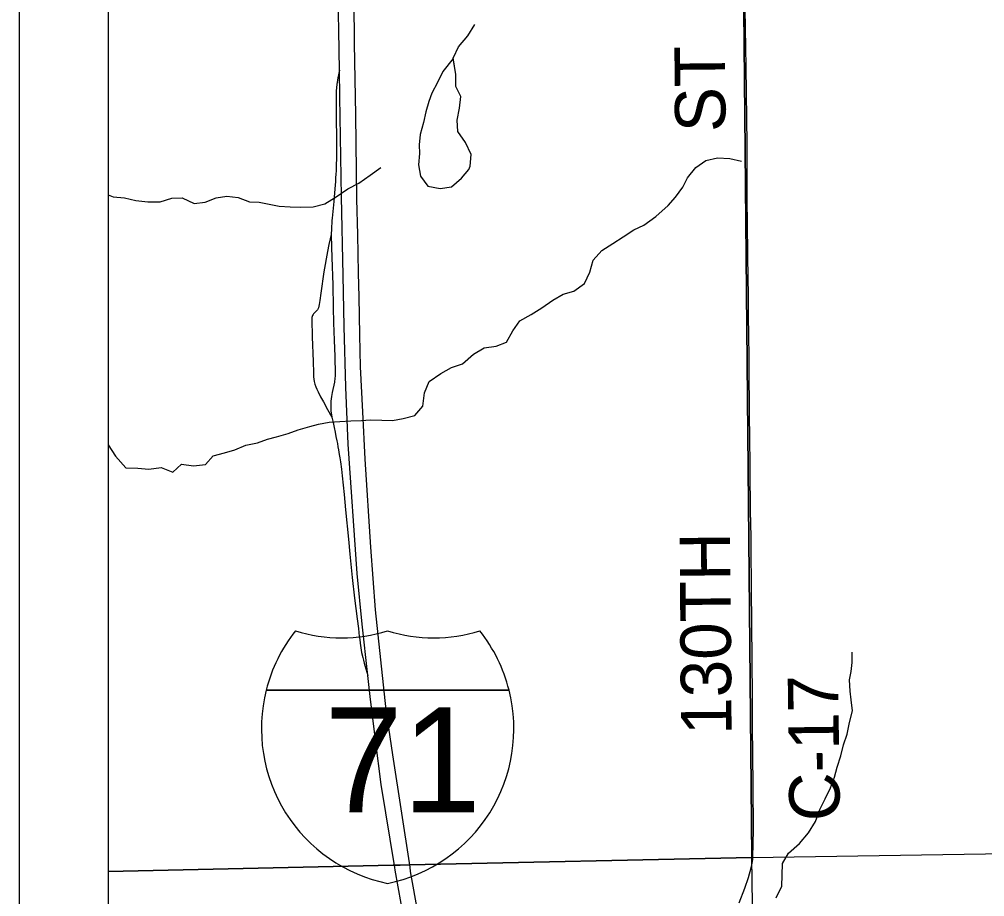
# Model space of a CAD drawing. Extents: x 0 to 34, y 0 to 22.
# Drawn here: x 2 to 3.087, y 18.988 to 19.975 of the extents above; entities that cross this region are included whole.
import ezdxf

# ---------------------------------------------------------------- set-up
doc = ezdxf.new("R2010")
doc.units = 0
for name, color, linetype in [('GM_X_Corporation', 7, 'Continuous'), ('GM_X_County_Road', 7, 'Continuous'), ('GM_X_County_Road_Text', 7, 'Continuous'), ('GM_X_Interchange_Ramps', 7, 'Continuous'), ('GM_X_Interstate_Location', 7, 'Continuous'), ('GM_X_Interstate_Route', 7, 'Continuous'), ('GM_X_Interstate_Shield', 7, 'Continuous'), ('GM_X_Minor_Lake', 7, 'Continuous'), ('GM_X_Minor_River', 7, 'Continuous'), ('SH_Data', 7, 'Continuous')]:
    doc.layers.add(name, color=color, linetype=linetype)

msp = doc.modelspace()

# ---------------------------------------------------------------- linework, layer by layer
at = {"layer": 'GM_X_Corporation'}
for points in [[(7.991, 17.7727), (7.9901, 18.1613), (7.988, 19.001), (7.9884, 19.0254), (7.9898, 19.1149), (7.9901, 19.6615), (7.9904, 20.2824), (7.9906, 20.6512), (7.9922, 20.9), (2.1, 20.9), (2.1, 14.1)], [(2.837, 17.9259), (2.8293, 18.7154), (2.8247, 19.0323), (3.279, 19.0395), (3.3208, 19.0402), (3.8964, 19.0508), (4.1999, 19.0575), (4.5008, 19.0629), (4.7704, 19.0672), (4.9094, 19.0728), (5.4081, 19.0763), (6.7986, 19.0964), (7.9898, 19.1149), (7.9884, 19.0254), (7.988, 19.001), (7.9901, 18.1613), (7.991, 17.7727)]]:
    msp.add_lwpolyline(points, dxfattribs=at)
for points in [[(2.8099, 20.9), (2.1, 20.9), (2.1, 19.0167), (2.421, 19.0236), (2.4288, 19.0238), (2.4392, 19.024), (2.8247, 19.0323), (2.8158, 19.9868), (2.8107, 20.774)], [(7.9922, 20.9), (2.8099, 20.9), (2.8107, 20.774), (2.8158, 19.9868), (2.8247, 19.0323), (3.279, 19.0395), (3.3208, 19.0402), (3.8964, 19.0508), (4.1999, 19.0575), (4.5008, 19.0629), (4.7704, 19.0672), (4.9094, 19.0728), (5.4081, 19.0763), (6.7986, 19.0964), (7.9898, 19.1149), (7.9901, 19.6615), (7.9904, 20.2824), (7.9906, 20.6512)], [(2.1, 19.0167), (2.1, 14.5179), (2.2213, 14.5194), (2.2958, 14.5199), (2.3573, 14.5203), (2.3767, 14.5206), (2.4262, 14.5205), (2.6122, 14.5212), (2.8483, 14.5213), (2.8655, 14.5214), (2.8502, 15.8768), (2.8488, 16.2), (2.8487, 16.2273), (2.8487, 16.232), (2.8477, 16.3135), (2.8476, 16.3157), (2.8477, 16.7834), (2.837, 17.9259), (2.8293, 18.7154), (2.8247, 19.0323), (2.4392, 19.024), (2.4288, 19.0238), (2.421, 19.0236)]]:
    msp.add_lwpolyline(points, close=True, dxfattribs=at)
at = {"layer": 'GM_X_County_Road'}
for points in [[(2.8254, 19.0279), (2.8257, 19.0303), (2.8259, 19.0328), (2.8265, 19.0634), (2.8264, 19.1137), (2.8259, 19.1469), (2.8256, 19.1804), (2.8253, 19.2135), (2.8248, 19.2951), (2.8246, 19.31), (2.8245, 19.32), (2.8244, 19.3294), (2.8238, 19.3863), (2.8235, 19.4144), (2.8234, 19.4148), (2.8232, 19.4277), (2.8229, 19.4625), (2.8228, 19.4698), (2.8227, 19.4807), (2.8226, 19.4974), (2.8218, 19.5781), (2.8217, 19.5933), (2.8213, 19.6217), (2.8211, 19.6394), (2.8209, 19.6592), (2.8208, 19.6668), (2.8206, 19.683), (2.8203, 19.711), (2.8202, 19.7219), (2.82, 19.7348), (2.8199, 19.7453), (2.8196, 19.7724), (2.8194, 19.835), (2.8185, 19.9221), (2.8174, 19.9871)], [(2.8106, 18.9811), (2.817, 18.9979), (2.8211, 19.0098), (2.824, 19.0205), (2.825, 19.026), (2.8254, 19.0279)]]:
    msp.add_lwpolyline(points, dxfattribs=at)
at = {"layer": 'GM_X_Interchange_Ramps'}
for points in [[(2.3604, 19.918), (2.3586, 19.9094), (2.3576, 19.9019), (2.3569, 19.8949), (2.3568, 19.88), (2.357, 19.8256), (2.3566, 19.8049), (2.3564, 19.8011), (2.3561, 19.7969), (2.3559, 19.7929), (2.3556, 19.7886), (2.355, 19.78), (2.3542, 19.7704), (2.3522, 19.7517), (2.3519, 19.7489), (2.3517, 19.7458), (2.3515, 19.7426), (2.3513, 19.7397), (2.3512, 19.7331), (2.3515, 19.7189), (2.352, 19.7073), (2.353, 19.6768), (2.3535, 19.6511), (2.3539, 19.6338), (2.3545, 19.6145), (2.3551, 19.596), (2.3554, 19.5893), (2.3557, 19.5829), (2.3555, 19.5738), (2.3553, 19.5715), (2.3547, 19.5671), (2.3524, 19.5556), (2.3515, 19.5508), (2.3508, 19.5458), (2.3506, 19.5403), (2.3509, 19.5348), (2.3519, 19.5279), (2.3532, 19.5217), (2.3545, 19.5161), (2.3556, 19.511), (2.3565, 19.5061), (2.3575, 19.5011), (2.3581, 19.4982), (2.3587, 19.4945), (2.3594, 19.4911), (2.3603, 19.4858), (2.3609, 19.4821), (2.3617, 19.4773), (2.3627, 19.4693), (2.3635, 19.4619), (2.3656, 19.4407), (2.3672, 19.4233), (2.3706, 19.3904), (2.3722, 19.3735), (2.3748, 19.3472), (2.3775, 19.3242), (2.3805, 19.3009), (2.3817, 19.2898), (2.3828, 19.2808), (2.3832, 19.2777), (2.3839, 19.2734), (2.3846, 19.2682), (2.3854, 19.2631), (2.3866, 19.2574), (2.3874, 19.2542), (2.3882, 19.2508), (2.3923, 19.2372)], [(2.3512, 19.7331), (2.3484, 19.7219), (2.3468, 19.7141), (2.343, 19.6912), (2.3393, 19.6671), (2.3382, 19.659), (2.3378, 19.6567), (2.3375, 19.6544), (2.3371, 19.6526), (2.3367, 19.6507), (2.3362, 19.6494), (2.3356, 19.6484), (2.3347, 19.6474), (2.3339, 19.6465), (2.3325, 19.6451), (2.3314, 19.6441), (2.3308, 19.6433), (2.3301, 19.6422), (2.3297, 19.6411), (2.3295, 19.64), (2.3293, 19.6376), (2.3298, 19.6181), (2.3307, 19.5905), (2.3311, 19.5778), (2.3314, 19.573), (2.3316, 19.5706), (2.3321, 19.5679), (2.3329, 19.5649), (2.334, 19.5617), (2.3351, 19.5592), (2.3365, 19.5561), (2.3392, 19.5507), (2.3423, 19.5451), (2.3471, 19.5364), (2.3519, 19.5279)]]:
    msp.add_lwpolyline(points, dxfattribs=at)
at = {"layer": 'GM_X_Interstate_Route'}
for points in [[(2.3773, 19.9621), (2.3769, 19.9819), (2.3763, 19.999), (2.3759, 20.0507), (2.3749, 20.0994), (2.3745, 20.1253), (2.3743, 20.135), (2.3737, 20.1693), (2.3732, 20.2102), (2.3728, 20.2568), (2.3713, 20.3002), (2.371, 20.3333), (2.37, 20.3729), (2.3689, 20.4151), (2.3665, 20.4623), (2.3643, 20.4961), (2.3613, 20.5298), (2.3583, 20.5629), (2.3552, 20.59), (2.3505, 20.6279), (2.3424, 20.6858), (2.3372, 20.7177), (2.3307, 20.7596), (2.329, 20.7708)], [(2.3597, 19.9628), (2.3594, 19.9817), (2.357, 20.1241), (2.3562, 20.1722), (2.3553, 20.2126), (2.3544, 20.2567), (2.3539, 20.3031), (2.3532, 20.3522), (2.3514, 20.4059), (2.35, 20.4413), (2.3479, 20.4739), (2.3448, 20.5139), (2.3417, 20.5463), (2.3389, 20.5765), (2.335, 20.6082), (2.3311, 20.6377), (2.3245, 20.6828), (2.3152, 20.7382), (2.3088, 20.7697)], [(2.4227, 19.0211), (2.4074, 19.1143), (2.4009, 19.1648), (2.3951, 19.2134), (2.3923, 19.2372), (2.3861, 19.2949), (2.3805, 19.3519), (2.3703, 19.4973), (2.3678, 19.5616), (2.3659, 19.6299), (2.3646, 19.6871), (2.3626, 19.7756), (2.3608, 19.8882), (2.3604, 19.918), (2.3597, 19.9628)], [(2.4399, 19.0214), (2.4204, 19.1477), (2.4132, 19.1984), (2.401, 19.311), (2.3957, 19.3815), (2.3893, 19.4803), (2.3866, 19.5336), (2.3843, 19.5844), (2.3833, 19.6204), (2.3825, 19.6631), (2.3819, 19.6899), (2.3812, 19.7333), (2.38, 19.7732), (2.3789, 19.8679), (2.3775, 19.9482), (2.3773, 19.9621)], [(2.5937, 17.9944), (2.5837, 18.054), (2.5752, 18.1037), (2.5712, 18.1292), (2.5613, 18.1887), (2.5535, 18.2381), (2.5468, 18.2792), (2.54, 18.3191), (2.5339, 18.3552), (2.5133, 18.4791), (2.5118, 18.4881), (2.4939, 18.5956), (2.477, 18.6934), (2.462, 18.7884), (2.449, 18.8665), (2.4416, 18.9107), (2.4333, 18.9618), (2.4233, 19.0179), (2.4227, 19.0211)], [(2.6074, 18.0208), (2.5891, 18.1314), (2.5653, 18.2758), (2.5579, 18.3176), (2.5479, 18.3781), (2.541, 18.4212), (2.5289, 18.4906), (2.5274, 18.4994), (2.5269, 18.5022), (2.521, 18.5396), (2.511, 18.601), (2.5002, 18.6641), (2.4942, 18.7001), (2.4752, 18.8212), (2.4671, 18.869), (2.4656, 18.8777), (2.4406, 19.0165), (2.4399, 19.0214)]]:
    msp.add_lwpolyline(points, dxfattribs=at)
at = {"layer": 'GM_X_Interstate_Shield'}
for p, q in [((2.2781, 19.2206), (2.5513, 19.2206)), ((2.5513, 19.2206), (2.2781, 19.2206)), ((2.5513, 19.2206), (2.2781, 19.2206))]:
    msp.add_line(p, q, dxfattribs=at)
for centre, start, end in [((2.4502, 19.1771), 141.669, 165.8066), ((2.3628, 19.457), 253.0091, 286.9909), ((2.4666, 19.457), 253.0091, 286.9909), ((2.3792, 19.1771), 14.1934, 38.331), ((2.4502, 19.1771), 165.8066, 258.463), ((2.3792, 19.1771), 281.537, 14.1934)]:
    msp.add_arc(centre, 0.1776, start, end, dxfattribs=at)
at = {"layer": 'GM_X_Minor_Lake'}
for points in [[(2.4885, 19.9314), (2.477, 19.9166), (2.4708, 19.9043), (2.4646, 19.8924), (2.461, 19.8829), (2.4578, 19.8714), (2.455, 19.8593), (2.4514, 19.8459), (2.4501, 19.8341), (2.4507, 19.8243), (2.4494, 19.8117), (2.4515, 19.7989), (2.46, 19.7876), (2.4737, 19.7852), (2.4865, 19.7869), (2.4977, 19.7966), (2.5062, 19.8063)], [(2.4883, 19.9312), (2.477, 19.9166), (2.4708, 19.9043), (2.4646, 19.8924), (2.461, 19.8829), (2.4578, 19.8714), (2.455, 19.8593), (2.4514, 19.8459), (2.4501, 19.8341), (2.4507, 19.8243), (2.4494, 19.8117), (2.4515, 19.7989), (2.46, 19.7876), (2.4737, 19.7852), (2.4865, 19.7869), (2.4977, 19.7966), (2.5062, 19.8063)], [(2.5062, 19.8063), (2.5077, 19.8101), (2.5089, 19.8234), (2.5023, 19.8369), (2.4937, 19.8493), (2.4931, 19.8618), (2.4955, 19.8755), (2.4972, 19.8885), (2.4913, 19.8997), (2.4915, 19.9134), (2.4883, 19.9322)], [(2.5062, 19.8063), (2.5077, 19.8101), (2.5089, 19.8234), (2.5023, 19.8369), (2.4937, 19.8493), (2.4931, 19.8618), (2.4955, 19.8755), (2.4972, 19.8885), (2.4913, 19.8997), (2.4915, 19.9134), (2.4885, 19.9314)]]:
    msp.add_lwpolyline(points, dxfattribs=at)
at = {"layer": 'GM_X_Minor_River'}
for points in [[(2.4889, 19.9323), (2.4943, 19.9446), (2.5051, 19.9569), (2.5128, 19.9696)], [(2.1, 19.4971), (2.1001, 19.4967), (2.1083, 19.484), (2.1198, 19.4709), (2.1335, 19.4704), (2.146, 19.4694), (2.1599, 19.4712), (2.1729, 19.4657), (2.1826, 19.475), (2.1962, 19.473), (2.2098, 19.4744), (2.2183, 19.4844), (2.2311, 19.4876), (2.2428, 19.4909), (2.2552, 19.4964), (2.268, 19.4989), (2.2793, 19.5029), (2.2895, 19.5057), (2.3026, 19.5094), (2.3139, 19.5134), (2.3271, 19.5174), (2.3369, 19.5198), (2.3489, 19.522), (2.3607, 19.5229), (2.3731, 19.5235), (2.3852, 19.5241), (2.395, 19.5247), (2.4083, 19.5245), (2.42, 19.524), (2.4321, 19.5264), (2.4453, 19.5297), (2.4542, 19.5401), (2.4562, 19.5553), (2.4616, 19.5679), (2.4747, 19.5769), (2.4867, 19.5836), (2.4991, 19.5879), (2.5114, 19.5988), (2.5234, 19.6058), (2.537, 19.6076), (2.5486, 19.612), (2.5556, 19.625), (2.5637, 19.6361), (2.5764, 19.6432), (2.5884, 19.6506), (2.6007, 19.6595), (2.6123, 19.6662), (2.6244, 19.6694), (2.6363, 19.678), (2.6425, 19.691), (2.6461, 19.7044), (2.6557, 19.7152), (2.6681, 19.7233), (2.68, 19.7308), (2.692, 19.7386), (2.7033, 19.7437), (2.7167, 19.7534), (2.7305, 19.7658), (2.7386, 19.7754), (2.7472, 19.7866), (2.7523, 19.7969), (2.7615, 19.8088), (2.7731, 19.8166), (2.7859, 19.8195), (2.7999, 19.8186), (2.8132, 19.8158)], [(2.1, 19.778), (2.1058, 19.7757), (2.1183, 19.7744), (2.1312, 19.7716), (2.1448, 19.77), (2.1585, 19.7702), (2.1716, 19.7742), (2.1834, 19.7744), (2.1967, 19.7682), (2.2092, 19.7696), (2.2216, 19.7747), (2.2336, 19.7765), (2.2465, 19.7748), (2.2591, 19.7701), (2.2701, 19.7695), (2.2796, 19.7678), (2.2925, 19.7653), (2.305, 19.7644), (2.3171, 19.7639), (2.3307, 19.7645), (2.3439, 19.7678), (2.3566, 19.7756), (2.3697, 19.7845), (2.3824, 19.7912), (2.3951, 19.8001), (2.4071, 19.8087)], [(2.852, 18.987), (2.8586, 19), (2.8587, 19.0125), (2.8593, 19.0255), (2.8659, 19.0373), (2.8785, 19.0482), (2.8885, 19.0601), (2.8963, 19.0728), (2.9013, 19.0861), (2.9072, 19.0984), (2.9134, 19.1106), (2.9177, 19.1225), (2.9209, 19.1339), (2.9248, 19.1465), (2.928, 19.1591), (2.932, 19.1709), (2.9348, 19.1842), (2.938, 19.1972), (2.9366, 19.2097), (2.9353, 19.2195), (2.9347, 19.232), (2.9364, 19.2416), (2.9378, 19.2515), (2.9375, 19.2632)]]:
    msp.add_lwpolyline(points, dxfattribs=at)
at = {"layer": 'SH_Data'}
for p, q in [((2, 21), (2, 14)), ((2.1, 20.9), (2.1, 14.1))]:
    msp.add_line(p, q, dxfattribs=at)

# ---------------------------------------------------------------- texts
at = {"layer": 'GM_X_County_Road_Text'}
for s, rotation, p in [('ST', 90.5903, (2.7953, 19.8487)), ('130TH', 90.4656, (2.802, 19.1704)), ('C-17', 90.6858, (2.9239, 19.0734))]:
    msp.add_text(s, height=0.05682, rotation=rotation, dxfattribs=at).set_placement(p)
at = {"layer": 'GM_X_Interstate_Location'}
for s in ['.', '-', ',']:
    msp.add_text(s, height=0.000189, dxfattribs=at).set_placement((2.4147, 19.145))
msp.add_text('71', height=0.000189, rotation=0, dxfattribs=at).set_placement((2.376, 19.1058))
at = {"layer": 'GM_X_Interstate_Shield'}
msp.add_text('71', height=0.11837, dxfattribs=at).set_placement((2.3435, 19.083))

doc.saveas('drawing.dxf')
